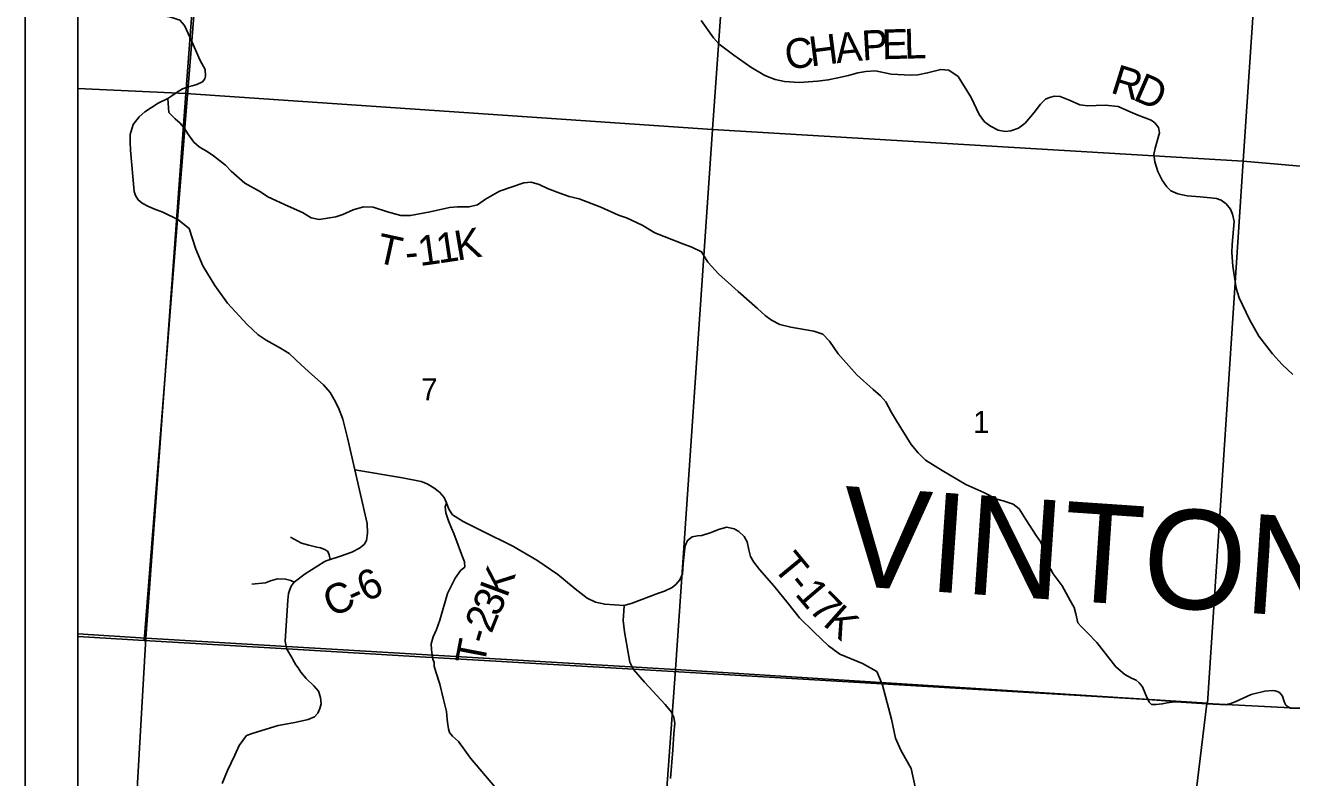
# Model space of a CAD drawing. Extents: x 0 to 34, y 0 to 22.
# Drawn here: x 2 to 4.418, y 15.517 to 16.952 of the extents above; entities that cross this region are included whole.
import ezdxf

# ---------------------------------------------------------------- set-up
doc = ezdxf.new("R2010")
doc.units = 0
for name, color, linetype in [('GM_X_Corporation', 7, 'Continuous'), ('GM_X_County_Road', 7, 'Continuous'), ('GM_X_County_Road_Text', 7, 'Continuous'), ('GM_X_County_Text', 7, 'Continuous'), ('GM_X_Section_Text', 7, 'Continuous'), ('GM_X_Township_Road', 7, 'Continuous'), ('GM_X_Township_Road_Text', 7, 'Continuous'), ('GM_X_Township_Text', 7, 'Continuous'), ('SH_Data', 7, 'Continuous')]:
    doc.layers.add(name, color=color, linetype=linetype)

msp = doc.modelspace()

# ---------------------------------------------------------------- linework, layer by layer
at = {"layer": 'GM_X_Corporation'}
msp.add_lwpolyline([(2.1, 20.9), (2.1, 14.1), (4.1481, 14.1), (4.1604, 14.3288), (4.1741, 14.5315), (4.1846, 14.6877), (4.2113, 15.0848), (4.2352, 15.4905), (4.2558, 15.6584), (4.2674, 15.6579), (4.2922, 15.6568), (4.4152, 15.6505), (4.4836, 15.6492), (5.4088, 15.5882), (6.2987, 15.5286), (6.3333, 15.9036), (6.368, 16.4127), (6.4323, 17.3579)], dxfattribs=at)
for points in [[(2.3791, 17.8483), (2.3793, 17.8512), (2.8467, 17.8245), (3.3856, 17.7912), (3.312, 16.7534), (2.3064, 16.8224), (2.3386, 17.2547), (2.3688, 17.6879)], [(3.3856, 17.7912), (4.3947, 17.724), (4.3249, 16.693), (3.312, 16.7534)], [(5.4208, 17.6557), (5.3461, 16.6042), (4.3249, 16.693), (4.3947, 17.724)], [(2.1, 16.832), (2.1, 15.7916), (2.2302, 15.7835), (2.3064, 16.8224)], [(3.312, 16.7534), (3.2411, 15.7231), (2.2302, 15.7835), (2.3064, 16.8224)], [(3.312, 16.7534), (4.3249, 16.693), (4.257, 15.6593), (3.2411, 15.7231)], [(2.1, 15.7916), (2.1, 14.7705), (2.1717, 14.7661), (2.2302, 15.7835)], [(2.2302, 15.7835), (3.2411, 15.7231), (3.1659, 14.6947), (2.1717, 14.7661)], [(4.1481, 14.1), (8.9, 14.1), (8.9, 15.3662), (8.5054, 15.3919), (7.8479, 15.4342), (7.082, 15.4841), (6.7558, 15.5053), (6.7389, 15.5063), (6.2987, 15.5286), (5.4088, 15.5882), (4.4836, 15.6492), (4.4152, 15.6505), (4.2922, 15.6568), (4.2674, 15.6579), (4.2558, 15.6584), (4.2352, 15.4905), (4.2113, 15.0848), (4.1846, 14.6877), (4.1741, 14.5315), (4.1604, 14.3288)]]:
    msp.add_lwpolyline(points, close=True, dxfattribs=at)
at = {"layer": 'GM_X_County_Road'}
for points in [[(2.3184, 16.8369), (2.3277, 16.8395), (2.338, 16.8445), (2.343, 16.8506), (2.344, 16.8563), (2.3435, 16.8683), (2.3341, 16.8856), (2.3179, 16.9213), (2.3037, 16.9519), (2.295, 16.9625), (2.2781, 16.9682), (2.2575, 16.9717), (2.244, 16.974), (2.2391, 16.9754)], [(3.2903, 16.9619), (3.3138, 16.9287), (3.3244, 16.9166), (3.3526, 16.8952), (3.3852, 16.8725), (3.4118, 16.8568), (3.4314, 16.8488), (3.4497, 16.8452), (3.4773, 16.8435), (3.4861, 16.8437), (3.5122, 16.8456), (3.533, 16.8482), (3.5514, 16.8525), (3.5714, 16.8566), (3.5896, 16.8619), (3.6049, 16.8646), (3.623, 16.8656), (3.6533, 16.8595), (3.6904, 16.8574), (3.7041, 16.8582), (3.7227, 16.8615), (3.7478, 16.8682), (3.7633, 16.8666), (3.7808, 16.8548), (3.8057, 16.8145), (3.8213, 16.7821), (3.8315, 16.7684), (3.8427, 16.7602), (3.8572, 16.7527), (3.8709, 16.75), (3.8815, 16.7511), (3.896, 16.7564), (3.9088, 16.766), (3.926, 16.7858), (3.9384, 16.8019), (3.948, 16.8115), (3.9556, 16.8147), (3.965, 16.8172), (3.9756, 16.8166), (3.995, 16.8088), (4.0133, 16.8005), (4.0287, 16.7986), (4.0442, 16.7992), (4.0619, 16.8003), (4.0864, 16.7978), (4.105, 16.7896), (4.1226, 16.7817), (4.1493, 16.7715), (4.1562, 16.7662), (4.1632, 16.7572), (4.1654, 16.7474), (4.1571, 16.7182), (4.1546, 16.7061), (4.1562, 16.6921), (4.1622, 16.6737), (4.1705, 16.6572), (4.1795, 16.6441), (4.1869, 16.6365), (4.2001, 16.6308), (4.2183, 16.6269), (4.2428, 16.6253), (4.2628, 16.6235), (4.2744, 16.6218), (4.2834, 16.6188), (4.2926, 16.612), (4.3006, 16.6018), (4.3048, 16.5924), (4.3079, 16.5782), (4.3038, 16.5341), (4.3036, 16.5188), (4.3055, 16.4932), (4.3118, 16.4508), (4.3177, 16.4328), (4.3373, 16.3914), (4.3551, 16.3593), (4.3808, 16.3258), (4.3996, 16.305), (4.4196, 16.286)], [(2.2594, 16.5972), (2.2485, 16.6011), (2.2352, 16.6069), (2.2231, 16.6132), (2.2152, 16.6193), (2.2103, 16.628), (2.2076, 16.6355), (2.2011, 16.7142), (2.2001, 16.7297), (2.1999, 16.7442), (2.2059, 16.7629), (2.2171, 16.7779), (2.2284, 16.7874), (2.2534, 16.804), (2.272, 16.8126), (2.2799, 16.8182), (2.2897, 16.8249), (2.3001, 16.8311), (2.3111, 16.8349), (2.3184, 16.8369)], [(2.5088, 15.7461), (2.4995, 15.7623), (2.496, 15.7775), (2.5012, 15.8555), (2.5024, 15.8684), (2.5044, 15.874), (2.5075, 15.8823), (2.5135, 15.8901), (2.5342, 15.906), (2.5704, 15.9289), (2.5744, 15.931), (2.5819, 15.9334), (2.5995, 15.9391), (2.6236, 15.9473), (2.638, 15.9548), (2.6467, 15.9619), (2.6514, 15.9693), (2.6534, 15.9835), (2.6529, 16.0022), (2.6291, 16.1046), (2.6149, 16.1654), (2.6062, 16.2008), (2.5977, 16.2228), (2.5896, 16.2384), (2.5818, 16.2521), (2.5692, 16.2665), (2.5471, 16.2865), (2.5266, 16.3047), (2.5038, 16.3262), (2.4871, 16.3367), (2.46, 16.3519), (2.4445, 16.3616), (2.4234, 16.3815), (2.3858, 16.4222), (2.3616, 16.4561), (2.3391, 16.4936), (2.3258, 16.5251), (2.3127, 16.5646), (2.291, 16.5819), (2.264, 16.5956), (2.2594, 16.5972)], [(2.3755, 15.5059), (2.386, 15.5306), (2.3997, 15.5599), (2.4082, 15.5782), (2.4224, 15.5973), (2.4348, 15.6019), (2.4826, 15.6165), (2.5148, 15.6225), (2.5402, 15.628), (2.5524, 15.6333), (2.5583, 15.6404), (2.562, 15.6492), (2.5646, 15.6577), (2.5638, 15.6698), (2.5598, 15.6818), (2.5506, 15.6925), (2.5362, 15.706), (2.5258, 15.7182), (2.5207, 15.7263), (2.5163, 15.7324), (2.5107, 15.7427), (2.5088, 15.7461)]]:
    msp.add_lwpolyline(points, dxfattribs=at)
at = {"layer": 'GM_X_Township_Road'}
for p, q in [((4.1963, 15.6617), (4.256, 15.6579)), ((4.4154, 15.6499), (4.4838, 15.6486))]:
    msp.add_line(p, q, dxfattribs=at)
for points in [[(2.272, 16.8126), (2.2741, 16.7861), (2.2863, 16.7743), (2.2956, 16.7659), (2.3047, 16.7549)], [(2.3047, 16.7549), (2.3103, 16.7451), (2.3219, 16.7293), (2.3318, 16.7207), (2.349, 16.7106), (2.3591, 16.7034), (2.3819, 16.6857), (2.3928, 16.6742), (2.4193, 16.6512), (2.4488, 16.6348), (2.4633, 16.6252), (2.5018, 16.6071), (2.5294, 16.5953), (2.546, 16.5852), (2.5609, 16.582), (2.5925, 16.5869), (2.6064, 16.5913), (2.6259, 16.6007), (2.6457, 16.606), (2.6642, 16.6058), (2.6914, 16.5965), (2.7166, 16.5898), (2.7354, 16.5898), (2.7726, 16.5967), (2.8101, 16.605), (2.8252, 16.6062), (2.8473, 16.6062), (2.8634, 16.6102), (2.8787, 16.6205), (2.9054, 16.6363), (2.9519, 16.6519), (2.9656, 16.6529), (2.9813, 16.6485), (2.9969, 16.6414), (3.0207, 16.6319), (3.0386, 16.626), (3.0577, 16.6214), (3.099, 16.6058), (3.1322, 16.59), (3.1476, 16.5854), (3.1775, 16.5709), (3.2017, 16.5568), (3.2553, 16.5355), (3.2728, 16.5292), (3.2911, 16.5201), (3.3031, 16.5006), (3.3107, 16.4926), (3.3235, 16.4785), (3.3612, 16.4444), (3.3976, 16.4122), (3.4127, 16.3987), (3.4249, 16.3899), (3.4405, 16.3819), (3.4618, 16.3768), (3.4868, 16.3718), (3.5053, 16.3686), (3.5226, 16.3634), (3.5354, 16.3499), (3.5518, 16.3255), (3.5876, 16.2857), (3.6185, 16.2573), (3.6326, 16.2458), (3.6429, 16.2344), (3.6539, 16.214), (3.6631, 16.198), (3.6913, 16.1527), (3.7046, 16.1367), (3.7189, 16.1229), (3.7507, 16.1033), (3.7955, 16.0761), (3.8298, 16.061), (3.8546, 16.0484), (3.8668, 16.045), (3.8858, 16.0391), (3.8976, 16.0299), (3.9102, 16.0094), (3.9302, 15.9791), (3.9386, 15.9663), (3.9469, 15.9439), (3.9527, 15.9236), (3.9625, 15.9061), (3.9795, 15.8832), (3.995, 15.855), (4.0026, 15.8419), (4.0057, 15.8299), (4.0097, 15.8125), (4.0167, 15.8047), (4.0278, 15.7931), (4.0455, 15.7747), (4.0823, 15.7283), (4.0991, 15.7136), (4.1122, 15.7066), (4.1208, 15.7031), (4.1265, 15.698), (4.1328, 15.6905), (4.1421, 15.669), (4.143, 15.6669)], [(3.1433, 15.8453), (3.1061, 15.8479), (3.0888, 15.8519), (3.0726, 15.8597), (3.0499, 15.8772), (3.0165, 15.9045), (2.9767, 15.9322), (2.9307, 15.9584), (2.8714, 15.9878), (2.8359, 16.0058), (2.8157, 16.0182), (2.8084, 16.0291), (2.8041, 16.0412), (2.7998, 16.0515), (2.7907, 16.062), (2.7798, 16.0701), (2.767, 16.0775), (2.7556, 16.0819), (2.7202, 16.0889), (2.6291, 16.1046)], [(2.7776, 15.7459), (2.7753, 15.7614), (2.7748, 15.7722), (2.7788, 15.7859), (2.785, 15.8), (2.7913, 15.8177), (2.806, 15.8684), (2.8204, 15.8976), (2.8316, 15.9132), (2.8389, 15.9189), (2.8382, 15.9286), (2.8348, 15.9385), (2.8182, 15.9828), (2.8137, 15.9932), (2.8076, 16.0072), (2.8028, 16.0224), (2.8013, 16.0339), (2.8041, 16.0412)], [(3.6367, 15.6935), (3.6358, 15.6955), (3.6257, 15.7195), (3.5983, 15.7351), (3.5551, 15.7526), (3.5337, 15.7687), (3.5053, 15.7953), (3.4778, 15.8218), (3.4567, 15.8493), (3.4291, 15.883), (3.4018, 15.9142), (3.3906, 15.9281), (3.3847, 15.9388), (3.3814, 15.9517), (3.3781, 15.9672), (3.3727, 15.9771), (3.3623, 15.9866), (3.3533, 15.9917), (3.3396, 15.9948), (3.3234, 15.9907), (3.3094, 15.9846), (3.2914, 15.9789), (3.2835, 15.9786), (3.2732, 15.9764), (3.2641, 15.9698), (3.2595, 15.9591), (3.2582, 15.9489), (3.2562, 15.9249), (3.2544, 15.9059), (3.2497, 15.8942), (3.2421, 15.8856), (3.2352, 15.8799), (3.2202, 15.873), (3.209, 15.8689), (3.1586, 15.8501), (3.1433, 15.8453)], [(2.5064, 15.9759), (2.5272, 15.9647), (2.5413, 15.9603), (2.5565, 15.9571), (2.5635, 15.9553), (2.5719, 15.9524), (2.5776, 15.9488), (2.5802, 15.942), (2.5819, 15.9334)], [(2.4325, 15.8861), (2.4583, 15.8887), (2.468, 15.8924), (2.4816, 15.8961), (2.497, 15.8958), (2.5071, 15.8934), (2.5135, 15.8901)], [(3.1612, 15.7234), (3.154, 15.7375), (3.1441, 15.7952), (3.1416, 15.8166), (3.1424, 15.8345), (3.1433, 15.8453)], [(2.8963, 15.4998), (2.8497, 15.5545), (2.8267, 15.5862), (2.8154, 15.5964), (2.8101, 15.6035), (2.8076, 15.6104), (2.8068, 15.6185), (2.8055, 15.6279), (2.8039, 15.6431), (2.7983, 15.6661), (2.7915, 15.6954), (2.7839, 15.7188), (2.7803, 15.73), (2.7803, 15.7368), (2.778, 15.7434), (2.7776, 15.7459)], [(3.2316, 15.5156), (3.2362, 15.5703), (3.238, 15.6004), (3.24, 15.6213), (3.2382, 15.6317), (3.2334, 15.6422), (3.2214, 15.6564), (3.1821, 15.6994), (3.1612, 15.7234)], [(3.704, 15.4762), (3.6913, 15.5343), (3.6864, 15.5433), (3.6716, 15.5692), (3.6613, 15.5922), (3.6539, 15.6284), (3.6367, 15.6935)], [(4.143, 15.6669), (4.1434, 15.6658), (4.1456, 15.6608), (4.1502, 15.6568), (4.1589, 15.6564), (4.1705, 15.6578), (4.1797, 15.6595), (4.1943, 15.6618), (4.1963, 15.6617)], [(4.2924, 15.6563), (4.2957, 15.6571), (4.2994, 15.658), (4.3098, 15.662), (4.3401, 15.6759), (4.3662, 15.6819), (4.3809, 15.6834), (4.3862, 15.6827), (4.3918, 15.6808), (4.3952, 15.6789), (4.3978, 15.6757), (4.4, 15.6723), (4.403, 15.6644), (4.4045, 15.6589), (4.4067, 15.6554), (4.41, 15.6526), (4.4154, 15.6499)], [(4.256, 15.6579), (4.2676, 15.6574), (4.2924, 15.6563)]]:
    msp.add_lwpolyline(points, dxfattribs=at)
at = {"layer": 'GM_X_Township_Text'}
for points in [[(2.227, 15.7788), (2.2908, 16.5824), (2.3045, 16.7554), (2.3047, 16.7573), (2.3109, 16.8355), (2.3177, 16.9219), (2.3436, 17.248), (2.3535, 17.3723), (2.3875, 17.8009), (2.3895, 17.8265), (2.4044, 18.0137), (2.4049, 18.0199), (2.4177, 18.1813), (2.4336, 18.4735), (2.4376, 18.5458), (2.4377, 18.5488), (2.4735, 18.8849), (2.5013, 19.2713), (2.5435, 19.8534), (2.5683, 20.2001), (2.5873, 20.4639), (2.6187, 20.9)], [(4.2558, 15.6584), (4.1941, 15.6624), (4.1432, 15.6663), (3.6356, 15.696), (3.161, 15.7239), (2.7774, 15.7464), (2.7647, 15.7472), (2.4993, 15.7628), (2.227, 15.7788), (2.1, 15.7864)], [(8.9, 15.3662), (8.5054, 15.3919), (7.8479, 15.4342), (7.082, 15.4841), (6.7558, 15.5053), (6.7389, 15.5063), (6.2987, 15.5286), (5.4088, 15.5882), (4.4836, 15.6492), (4.4152, 15.6505), (4.2922, 15.6568), (4.2674, 15.6579), (4.2558, 15.6584), (4.2352, 15.4905), (4.2113, 15.0848), (4.1846, 14.6877), (4.1741, 14.5315), (4.1604, 14.3288), (4.1481, 14.1)]]:
    msp.add_lwpolyline(points, dxfattribs=at)
at = {"layer": 'SH_Data'}
for p, q in [((2, 21), (2, 14)), ((2.1, 20.9), (2.1, 14.1))]:
    msp.add_line(p, q, dxfattribs=at)

# ---------------------------------------------------------------- texts
at = {"layer": 'GM_X_County_Road_Text'}
for s, rotation, p in [('C', 7.3612, (3.4536, 16.8677)), ('H', 7.3527, (3.4999, 16.8737)), ('A', 6.1427, (3.5492, 16.88)), ('P', 3.4376, (3.5982, 16.8853)), ('E', 1.5302, (3.636, 16.8876)), ('L', 1.2986, (3.6784, 16.8887)), ('R', 342.6981, (4.0697, 16.8244)), ('D', 336.4403, (4.1127, 16.8111)), ('6', 24.997, (2.6498, 15.8513)), ('C', 23.5824, (2.5843, 15.8225)), ('-', 23.7662, (2.6273, 15.8413))]:
    msp.add_text(s, height=0.0568, rotation=rotation, dxfattribs=at).set_placement(p)
at = {"layer": 'GM_X_County_Text'}
msp.add_text('VINTON COUNTY', height=0.189394, rotation=356.1113, dxfattribs=at).set_placement((3.553, 15.8845))
at = {"layer": 'GM_X_Section_Text'}
for s, p in [('7', (2.7557, 16.2369)), ('1', (3.8094, 16.1748))]:
    msp.add_text(s, height=0.0419, rotation=0, dxfattribs=at).set_placement(p)
at = {"layer": 'GM_X_Township_Road_Text'}
for s, rotation, p in [('K', 9.5203, (2.8243, 16.5032)), ('T', 347.5521, (2.6667, 16.5009)), ('1', 7.8882, (2.7533, 16.493)), ('1', 8.4932, (2.7886, 16.4979)), ('-', 5.1612, (2.7271, 16.4906)), ('T', 309.4281, (3.4255, 15.9182)), ('K', 69.5722, (2.9194, 15.8586)), ('-', 309.469, (3.4525, 15.8854)), ('1', 310.4153, (3.4678, 15.8668)), ('3', 64.8803, (2.9026, 15.8222)), ('7', 314.6907, (3.4934, 15.837)), ('2', 68.1271, (2.8899, 15.7905)), ('K', 318.5156, (3.5209, 15.8094)), ('-', 73.6364, (2.8838, 15.7695)), ('T', 79.1616, (2.8761, 15.7292))]:
    msp.add_text(s, height=0.0568, rotation=rotation, dxfattribs=at).set_placement(p)

doc.saveas('drawing.dxf')
